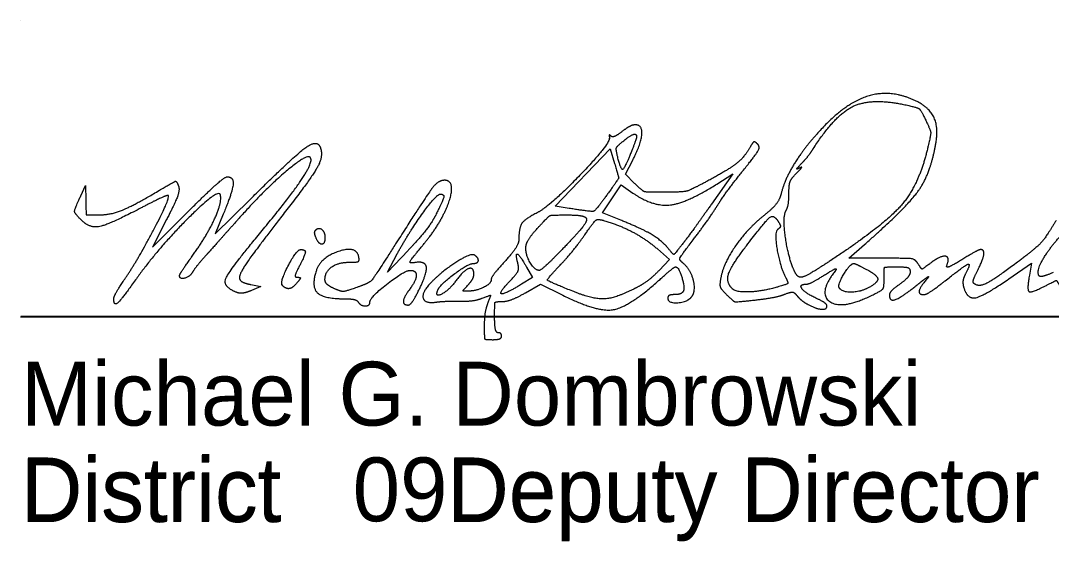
# Model space of a CAD drawing. Extents: x 0 to 82.7, y -0.2 to 22.
# Drawn here: x 75.688 to 77.95, y 7.73 to 8.873 of the extents above; entities that cross this region are included whole.
import ezdxf

# ---------------------------------------------------------------- set-up
doc = ezdxf.new("R2010")
doc.units = 0
doc.layers.add('SH_Data', color=7, linetype='Continuous')
doc.layers.add('SH_Text', color=7, linetype='Continuous')

msp = doc.modelspace()

# ---------------------------------------------------------------- linework, layer by layer
at = {"layer": 'SH_Data'}
for p, q in [((75.6876, 8.8727), (75.6876, 8.8727)), ((75.6876, 8.8727), (75.6876, 8.8727)), ((75.6876, 8.2227), (79.1876, 8.2227)), ((75.6883, 8.2245), (79.1883, 8.2245))]:
    msp.add_line(p, q, dxfattribs=at)
at = {"layer": 'SH_Text'}
for p, q in [((76.3356, 8.3975), (76.3356, 8.3975)), ((76.2623, 8.2917), (76.2623, 8.2917)), ((75.8921, 8.2634), (75.8921, 8.2634))]:
    msp.add_line(p, q, dxfattribs=at)
for points in [[(76.8915, 8.4609), (76.8611, 8.4657), (76.982, 8.5914), (76.9915, 8.5593)], [(77.0354, 8.5158), (77.0156, 8.5357), (77.0314, 8.5668)], [(77.2159, 8.5142), (77.251, 8.5365), (77.2043, 8.4704)], [(75.8197, 8.4883), (75.8301, 8.5111), (75.8307, 8.4788)], [(77.0049, 8.4351), (76.9646, 8.4514), (76.9851, 8.4818), (77.0055, 8.5122), (77.0314, 8.4946)], [(76.1326, 8.4483), (76.1146, 8.4047), (76.1915, 8.4807)], [(76.008, 8.4363), (75.9768, 8.3756), (76.0543, 8.4529)], [(77.0853, 8.3721), (77.1119, 8.3491), (77.0891, 8.3249)], [(77.5777, 8.3515), (77.5056, 8.3515), (77.5403, 8.3819)], [(76.5381, 8.3687), (76.4927, 8.3211), (76.5135, 8.3598)], [(76.7982, 8.3322), (76.8113, 8.3092), (76.7868, 8.2943)], [(77.8566, 8.3061), (77.9069, 8.3406), (77.902, 8.3146)], [(76.193, 8.2938), (76.2151, 8.2894), (76.1943, 8.2808)], [(76.7956, 8.2757), (76.8289, 8.2948), (76.8747, 8.2718)]]:
    msp.add_lwpolyline(points, dxfattribs=at)
for points in [[(77.6553, 8.6952), (77.5985, 8.7236), (77.4932, 8.6895), (77.4355, 8.624)], [(77.4273, 8.5915), (77.4744, 8.6652), (77.5549, 8.7039), (77.6283, 8.6883)], [(77.6283, 8.6883), (77.6559, 8.6824), (77.6638, 8.6766), (77.6743, 8.6545)], [(77.6971, 8.6061), (77.7025, 8.6389), (77.6824, 8.6817), (77.6553, 8.6952)], [(77.037, 8.6441), (77.0312, 8.6441), (77.018, 8.6374), (77.0076, 8.6292)], [(77.0314, 8.5668), (77.0497, 8.6026), (77.0527, 8.6441), (77.037, 8.6441)], [(77.6743, 8.6545), (77.6851, 8.6318), (77.6856, 8.6223), (77.678, 8.5904)], [(76.9831, 8.6197), (76.9801, 8.6227), (76.9788, 8.6214), (76.9802, 8.6169)], [(77.0076, 8.6292), (76.9971, 8.621), (76.9861, 8.6167), (76.9831, 8.6197)], [(77.0096, 8.6079), (77.0255, 8.6208), (77.0397, 8.6254), (77.0397, 8.6177)], [(77.4355, 8.624), (77.4019, 8.5858), (77.3639, 8.522), (77.3563, 8.4909)], [(76.1915, 8.4807), (76.286, 8.574), (76.3384, 8.6129), (76.3453, 8.5948)], [(76.9802, 8.6169), (76.9838, 8.6051), (76.8507, 8.4663), (76.8215, 8.4513)], [(76.9982, 8.5737), (76.9941, 8.5898), (76.9967, 8.5974), (77.0096, 8.6079)], [(77.0397, 8.6177), (77.0397, 8.6157), (77.0342, 8.6003), (77.0275, 8.5835)], [(77.2744, 8.5449), (77.3023, 8.5797), (77.3112, 8.5961), (77.3054, 8.6018)], [(77.3054, 8.6018), (77.2996, 8.6076), (77.295, 8.606), (77.2896, 8.5965)], [(77.5403, 8.3819), (77.6326, 8.4626), (77.686, 8.539), (77.6971, 8.6061)], [(76.3453, 8.5948), (76.3523, 8.5768), (76.3302, 8.5336), (76.2835, 8.4731)], [(77.0275, 8.5835), (77.0132, 8.5477), (77.0054, 8.5451), (76.9982, 8.5737)], [(77.2896, 8.5965), (77.2765, 8.5733), (77.2433, 8.5466), (77.1958, 8.5211)], [(77.4007, 8.5584), (77.4091, 8.5668), (77.4211, 8.5817), (77.4273, 8.5915)], [(77.678, 8.5904), (77.6591, 8.5118), (77.5826, 8.4237), (77.4663, 8.3468)], [(76.3233, 8.5727), (76.3156, 8.5804), (76.2246, 8.5034), (76.1721, 8.4447)], [(76.2302, 8.4275), (76.2844, 8.4929), (76.3308, 8.5652), (76.3233, 8.5727)], [(76.9915, 8.5593), (77.0007, 8.5283), (77.0001, 8.5259), (76.9762, 8.4925)], [(77.3969, 8.5491), (77.3907, 8.5458), (77.3924, 8.55), (77.4007, 8.5584)], [(76.0543, 8.4529), (76.0969, 8.4954), (76.136, 8.5301), (76.1412, 8.5301)], [(76.1412, 8.5301), (76.1558, 8.5301), (76.1522, 8.4959), (76.1326, 8.4483)], [(77.2161, 8.4656), (77.2266, 8.4824), (77.2529, 8.5181), (77.2744, 8.5449)], [(77.374, 8.4937), (77.3741, 8.5129), (77.3796, 8.5273), (77.3912, 8.5386)], [(77.3912, 8.5386), (77.4006, 8.5477), (77.4032, 8.5525), (77.3969, 8.5491)], [(75.9923, 8.5005), (76.0252, 8.52), (76.03, 8.521), (76.0343, 8.5097)], [(76.0343, 8.5097), (76.0373, 8.502), (76.0269, 8.473), (76.008, 8.4363)], [(76.6183, 8.5225), (76.6043, 8.5225), (76.5785, 8.4889), (76.5108, 8.3829)], [(76.6134, 8.4426), (76.6321, 8.4782), (76.6349, 8.5225), (76.6183, 8.5225)], [(77.0314, 8.4946), (77.0756, 8.4644), (77.1498, 8.4723), (77.2159, 8.5142)], [(77.1026, 8.4962), (77.0616, 8.496), (77.0527, 8.4986), (77.0354, 8.5158)], [(77.1958, 8.5211), (77.1584, 8.501), (77.1412, 8.4964), (77.1026, 8.4962)], [(75.8212, 8.4349), (75.8061, 8.4501), (75.8059, 8.4582), (75.8197, 8.4883)], [(75.857, 8.4465), (75.8848, 8.4465), (75.9339, 8.4661), (75.9923, 8.5005)], [(75.9196, 8.3109), (75.9493, 8.355), (76.0164, 8.4844), (76.0119, 8.4889)], [(76.1263, 8.4901), (76.1231, 8.5068), (75.9894, 8.3734), (75.9399, 8.3041)], [(76.0119, 8.4889), (76.0103, 8.4904), (75.9835, 8.4783), (75.9521, 8.4619)], [(76.063, 8.3542), (76.0959, 8.3999), (76.1297, 8.4725), (76.1263, 8.4901)], [(76.5135, 8.3598), (76.538, 8.4052), (76.6002, 8.4919), (76.6084, 8.4921)], [(76.6084, 8.4921), (76.6179, 8.4922), (76.6149, 8.4779), (76.5988, 8.4463)], [(76.9762, 8.4925), (76.9502, 8.4563), (76.9413, 8.4529), (76.8915, 8.4609)], [(77.3563, 8.4909), (77.3536, 8.4798), (77.3375, 8.4597), (77.3206, 8.4463)], [(77.3677, 8.4557), (77.3711, 8.4611), (77.374, 8.4782), (77.374, 8.4937)], [(75.8307, 8.4788), (75.8313, 8.4473), (75.832, 8.4465), (75.857, 8.4465)], [(76.2835, 8.4731), (76.2058, 8.3728), (76.1654, 8.3145), (76.1681, 8.3064)], [(77.2043, 8.4704), (77.1786, 8.4341), (77.1502, 8.395), (77.1412, 8.3836)], [(77.1641, 8.3922), (77.1822, 8.4158), (77.2056, 8.4489), (77.2161, 8.4656)], [(75.9521, 8.4619), (75.8828, 8.4255), (75.8395, 8.4166), (75.8212, 8.4349)], [(76.1721, 8.4447), (76.1414, 8.4103), (76.1061, 8.3707), (76.0935, 8.3567)], [(76.5988, 8.4463), (76.5904, 8.4298), (76.5631, 8.3949), (76.5381, 8.3687)], [(76.5669, 8.3757), (76.5837, 8.3958), (76.6046, 8.426), (76.6134, 8.4426)], [(76.8215, 8.4513), (76.7948, 8.4376), (76.7813, 8.4184), (76.7813, 8.3937)], [(76.8228, 8.418), (76.8463, 8.4437), (76.8528, 8.4465), (76.8869, 8.4465)], [(76.8869, 8.4465), (76.9078, 8.4465), (76.927, 8.443), (76.9296, 8.4388)], [(77.3206, 8.4463), (77.2844, 8.4176), (77.2313, 8.3423), (77.225, 8.3107)], [(77.281, 8.379), (77.3237, 8.435), (77.341, 8.4479), (77.3511, 8.4315)], [(77.383, 8.3306), (77.3707, 8.3621), (77.3606, 8.4446), (77.3677, 8.4557)], [(76.1626, 8.2763), (76.1299, 8.2889), (76.1469, 8.327), (76.2302, 8.4275)], [(76.3353, 8.4134), (76.3419, 8.4201), (76.3557, 8.4088), (76.3557, 8.3967)], [(76.7966, 8.3741), (76.7966, 8.3826), (76.8084, 8.4024), (76.8228, 8.418)], [(76.9296, 8.4388), (76.9323, 8.4345), (76.9114, 8.4071), (76.8832, 8.378)], [(76.9259, 8.4029), (76.9461, 8.4318), (76.9544, 8.4382), (76.967, 8.4345)], [(76.967, 8.4345), (77.0027, 8.424), (77.0604, 8.3936), (77.0853, 8.3721)], [(77.1082, 8.3742), (77.0945, 8.3907), (77.051, 8.4163), (77.0049, 8.4351)], [(77.3511, 8.4315), (77.3556, 8.4245), (77.3552, 8.4185), (77.3502, 8.4154)], [(77.9607, 8.4346), (77.9382, 8.397), (77.9164, 8.3735), (77.876, 8.3431)], [(76.3356, 8.3975), (76.3331, 8.4039), (76.333, 8.4111), (76.3353, 8.4134)], [(76.3557, 8.3967), (76.3557, 8.3821), (76.3412, 8.3827), (76.3356, 8.3975)], [(76.8736, 8.3382), (76.8885, 8.3539), (76.912, 8.383), (76.9259, 8.4029)], [(77.3502, 8.4154), (77.3418, 8.4102), (77.3542, 8.3334), (77.3674, 8.3082)], [(77.9239, 8.3123), (77.9154, 8.3207), (77.9481, 8.3777), (77.9812, 8.4123)], [(76.5108, 8.3829), (76.4632, 8.3083), (76.4532, 8.297), (76.4258, 8.2874)], [(76.5495, 8.3415), (76.5403, 8.3398), (76.5456, 8.3502), (76.5669, 8.3757)], [(76.7813, 8.3937), (76.7813, 8.3849), (76.7676, 8.363), (76.7509, 8.3448)], [(76.8261, 8.3249), (76.8162, 8.3249), (76.7965, 8.3577), (76.7966, 8.3741)], [(76.8832, 8.378), (76.8551, 8.3488), (76.8294, 8.3249), (76.8261, 8.3249)], [(77.1412, 8.3836), (77.1223, 8.3596), (77.1207, 8.3592), (77.1082, 8.3742)], [(77.1424, 8.3401), (77.1329, 8.348), (77.1361, 8.3556), (77.1641, 8.3922)], [(77.25, 8.2844), (77.2355, 8.2989), (77.2473, 8.3348), (77.281, 8.379)], [(76.0365, 8.3135), (76.0365, 8.3156), (76.0485, 8.3339), (76.063, 8.3542)], [(76.0935, 8.3567), (76.081, 8.3427), (76.068, 8.3264), (76.0647, 8.3205)], [(76.2623, 8.2917), (76.256, 8.298), (76.2931, 8.3705), (76.3027, 8.3705)], [(76.3027, 8.3705), (76.3133, 8.3705), (76.3119, 8.3581), (76.2985, 8.3322)], [(76.4299, 8.3547), (76.4247, 8.3796), (76.3457, 8.3531), (76.3362, 8.3233)], [(76.4093, 8.3427), (76.4263, 8.3427), (76.4317, 8.3458), (76.4299, 8.3547)], [(76.6836, 8.3584), (76.6763, 8.363), (76.6192, 8.3278), (76.5928, 8.3024)], [(76.6814, 8.3401), (76.6916, 8.3401), (76.6931, 8.3526), (76.6836, 8.3584)], [(76.7792, 8.3397), (76.7733, 8.3626), (76.7832, 8.3587), (76.7982, 8.3322)], [(77.6578, 8.339), (77.6514, 8.3492), (77.6365, 8.3515), (77.5777, 8.3515)], [(77.7208, 8.3358), (77.7278, 8.3541), (77.7077, 8.3576), (77.6864, 8.3418)], [(77.7949, 8.3705), (77.7922, 8.3705), (77.7735, 8.3604), (77.7534, 8.348)], [(77.7878, 8.3239), (77.8, 8.3476), (77.8035, 8.3705), (77.7949, 8.3705)], [(76.2985, 8.3322), (76.2907, 8.3169), (76.2897, 8.3097), (76.2957, 8.3097)], [(76.3557, 8.3046), (76.3557, 8.3219), (76.3849, 8.3427), (76.4093, 8.3427)], [(76.5627, 8.2834), (76.581, 8.321), (76.5752, 8.3462), (76.5495, 8.3415)], [(76.6036, 8.2821), (76.6084, 8.2938), (76.6705, 8.3401), (76.6814, 8.3401)], [(76.6825, 8.316), (76.6825, 8.3327), (76.6603, 8.325), (76.6438, 8.3028)], [(76.7509, 8.3448), (76.7342, 8.3267), (76.7205, 8.3085), (76.7205, 8.3044)], [(76.7619, 8.3017), (76.7764, 8.3168), (76.782, 8.3291), (76.7792, 8.3397)], [(76.8998, 8.279), (76.8446, 8.3012), (76.8427, 8.3055), (76.8736, 8.3382)], [(77.0911, 8.3052), (77.1077, 8.3202), (77.1232, 8.3325), (77.1254, 8.3325)], [(77.1254, 8.3325), (77.1321, 8.3325), (77.1463, 8.2857), (77.1418, 8.2785)], [(77.1602, 8.2665), (77.1704, 8.2788), (77.1588, 8.3264), (77.1424, 8.3401)], [(77.4007, 8.3097), (77.3954, 8.3097), (77.3875, 8.3191), (77.383, 8.3306)], [(77.4663, 8.3468), (77.4354, 8.3264), (77.4059, 8.3097), (77.4007, 8.3097)], [(77.4522, 8.3148), (77.4699, 8.3259), (77.4806, 8.3302), (77.476, 8.3243)], [(77.4844, 8.2868), (77.4805, 8.2931), (77.5088, 8.3401), (77.5165, 8.3401)], [(77.5165, 8.3401), (77.518, 8.3401), (77.5294, 8.3349), (77.5417, 8.3285)], [(77.5417, 8.3285), (77.5675, 8.3152), (77.5706, 8.2985), (77.5494, 8.2872)], [(77.5831, 8.3061), (77.5831, 8.3312), (77.5848, 8.3325), (77.6173, 8.3325)], [(77.6173, 8.3325), (77.632, 8.3325), (77.6401, 8.3287), (77.6401, 8.3217)], [(77.6864, 8.3418), (77.6674, 8.3278), (77.665, 8.3276), (77.6578, 8.339)], [(77.717, 8.3021), (77.7597, 8.3358), (77.7742, 8.3407), (77.7616, 8.317)], [(77.7534, 8.348), (77.7333, 8.3356), (77.7186, 8.3302), (77.7208, 8.3358)], [(77.876, 8.3431), (77.825, 8.3048), (77.7891, 8.2874), (77.7798, 8.2967)], [(75.8921, 8.2634), (75.8921, 8.2671), (75.9045, 8.2885), (75.9196, 8.3109)], [(75.9399, 8.3041), (75.9087, 8.2603), (75.8921, 8.2462), (75.8921, 8.2634)], [(76.0647, 8.3205), (76.059, 8.3105), (76.0365, 8.305), (76.0365, 8.3135)], [(76.1681, 8.3064), (76.1696, 8.302), (76.1808, 8.2963), (76.193, 8.2938)], [(76.2957, 8.3097), (76.3019, 8.3097), (76.3017, 8.3065), (76.2949, 8.2983)], [(76.3362, 8.3233), (76.3254, 8.2891), (76.3526, 8.2626), (76.3985, 8.2626)], [(76.3753, 8.2853), (76.3645, 8.2902), (76.3557, 8.2989), (76.3557, 8.3046)], [(76.4545, 8.2559), (76.4545, 8.2657), (76.5303, 8.3249), (76.5429, 8.3249)], [(76.5429, 8.3249), (76.5565, 8.3249), (76.5558, 8.3023), (76.5417, 8.2836)], [(76.7205, 8.3044), (76.7205, 8.2957), (76.6873, 8.2793), (76.6696, 8.2793)], [(76.67, 8.2932), (76.6769, 8.3009), (76.6825, 8.3111), (76.6825, 8.316)], [(76.8747, 8.2718), (76.9523, 8.2331), (77.0234, 8.244), (77.0911, 8.3052)], [(77.0891, 8.3249), (77.0766, 8.3116), (77.0533, 8.294), (77.0373, 8.2858)], [(77.225, 8.3107), (77.2216, 8.294), (77.2247, 8.2843), (77.2374, 8.2716)], [(77.3674, 8.3082), (77.3731, 8.2976), (77.3692, 8.2939), (77.3457, 8.2874)], [(77.4116, 8.2945), (77.4163, 8.2945), (77.4345, 8.3036), (77.4522, 8.3148)], [(77.476, 8.3243), (77.4372, 8.2742), (77.491, 8.2381), (77.5565, 8.2704)], [(77.5565, 8.2704), (77.578, 8.2809), (77.5831, 8.2878), (77.5831, 8.3061)], [(77.6401, 8.3217), (77.6401, 8.3157), (77.6299, 8.3035), (77.6173, 8.2945)], [(77.6545, 8.2923), (77.6738, 8.3077), (77.6835, 8.3134), (77.6762, 8.305)], [(77.6762, 8.305), (77.6614, 8.2878), (77.6588, 8.2717), (77.6708, 8.2717)], [(77.7616, 8.317), (77.757, 8.3085), (77.7554, 8.2948), (77.758, 8.2866)], [(77.758, 8.2866), (77.7661, 8.2613), (77.8012, 8.2682), (77.8566, 8.3061)], [(77.7798, 8.2967), (77.7776, 8.2989), (77.7812, 8.3111), (77.7878, 8.3239)], [(77.902, 8.3146), (77.8959, 8.2819), (77.9062, 8.275), (77.9375, 8.2912)], [(77.9541, 8.32), (77.9393, 8.3139), (77.9257, 8.3104), (77.9239, 8.3123)], [(76.2949, 8.2983), (76.2851, 8.2865), (76.2705, 8.2835), (76.2623, 8.2917)], [(76.4258, 8.2874), (76.4013, 8.2787), (76.3907, 8.2783), (76.3753, 8.2853)], [(76.5417, 8.2836), (76.5288, 8.2665), (76.527, 8.2489), (76.5382, 8.2489)], [(76.5382, 8.2489), (76.5425, 8.2489), (76.5535, 8.2645), (76.5627, 8.2834)], [(76.5928, 8.3024), (76.5691, 8.2796), (76.5727, 8.2518), (76.5989, 8.2552)], [(76.6438, 8.3028), (76.6276, 8.2809), (76.5966, 8.2649), (76.6036, 8.2821)], [(76.6696, 8.2793), (76.6585, 8.2793), (76.6585, 8.2806), (76.67, 8.2932)], [(76.7868, 8.2943), (76.7496, 8.2716), (76.7368, 8.2754), (76.7619, 8.3017)], [(77.0373, 8.2858), (76.9941, 8.2636), (76.9442, 8.2611), (76.8998, 8.279)], [(77.3457, 8.2874), (77.3136, 8.2784), (77.2577, 8.2767), (77.25, 8.2844)], [(77.4333, 8.2641), (77.4092, 8.2755), (77.3957, 8.2945), (77.4116, 8.2945)], [(77.5494, 8.2872), (77.5308, 8.2772), (77.4905, 8.277), (77.4844, 8.2868)], [(77.6173, 8.2945), (77.6048, 8.2856), (77.5945, 8.2751), (77.5945, 8.2712)], [(77.5945, 8.2712), (77.5945, 8.2561), (77.6211, 8.2654), (77.6545, 8.2923)], [(77.6708, 8.2717), (77.6751, 8.2717), (77.6959, 8.2854), (77.717, 8.3021)], [(77.9375, 8.2912), (77.9596, 8.3027), (77.9622, 8.3027), (77.9685, 8.2915)], [(76.1943, 8.2808), (76.1828, 8.276), (76.1686, 8.274), (76.1626, 8.2763)], [(76.3985, 8.2626), (76.4126, 8.2626), (76.4261, 8.2595), (76.4284, 8.2558)], [(76.6497, 8.2571), (76.6671, 8.2568), (76.6901, 8.2598), (76.7007, 8.2638)], [(76.7007, 8.2638), (76.719, 8.2708), (76.7196, 8.2702), (76.7126, 8.2519)], [(76.7452, 8.2566), (76.7546, 8.2567), (76.7773, 8.2653), (76.7956, 8.2757)], [(77.1229, 8.2717), (77.1148, 8.2717), (77.1081, 8.2683), (77.1081, 8.2641)], [(77.1081, 8.2641), (77.1081, 8.2529), (77.1505, 8.2549), (77.1602, 8.2665)], [(77.1418, 8.2785), (77.1395, 8.2748), (77.131, 8.2717), (77.1229, 8.2717)], [(77.2374, 8.2716), (77.2525, 8.2566), (77.2591, 8.2553), (77.2997, 8.2599)], [(77.2997, 8.2599), (77.3247, 8.2627), (77.3538, 8.2683), (77.3644, 8.2724)], [(77.3644, 8.2724), (77.3787, 8.2778), (77.3858, 8.2769), (77.3922, 8.269)], [(77.3922, 8.269), (77.3969, 8.2632), (77.4076, 8.2547), (77.4159, 8.2501)], [(77.4576, 8.247), (77.4575, 8.2502), (77.4465, 8.2579), (77.4333, 8.2641)], [(76.4284, 8.2558), (76.4339, 8.2468), (76.4545, 8.2469), (76.4545, 8.2559)], [(76.5989, 8.2552), (76.6094, 8.2566), (76.6322, 8.2575), (76.6497, 8.2571)], [(76.7126, 8.2519), (76.7086, 8.2414), (76.7053, 8.2193), (76.7053, 8.2028)], [(76.7281, 8.2223), (76.7281, 8.2527), (76.73, 8.2565), (76.7452, 8.2566)], [(77.4159, 8.2501), (77.4335, 8.2405), (77.4578, 8.2387), (77.4576, 8.247)], [(76.7357, 8.1881), (76.7315, 8.1881), (76.7281, 8.2035), (76.7281, 8.2223)], [(76.7053, 8.2028), (76.7053, 8.176), (76.7073, 8.1729), (76.7243, 8.1729)], [(76.7243, 8.1729), (76.7348, 8.1729), (76.7433, 8.1764), (76.7433, 8.1805)], [(76.7433, 8.1805), (76.7433, 8.1847), (76.7399, 8.1881), (76.7357, 8.1881)]]:
    msp.add_open_spline(points, degree=2, dxfattribs=at)

# ---------------------------------------------------------------- texts
for s, p in [('Michael G. Dombrowski', (75.6883, 7.9845)), ('District       Deputy Director', (75.6876, 7.7727)), ('District       Deputy Director', (75.6883, 7.7745)), ('              09', (75.6883, 7.7745))]:
    msp.add_text(s, height=0.14, dxfattribs=at).set_placement(p)

doc.saveas('drawing.dxf')
